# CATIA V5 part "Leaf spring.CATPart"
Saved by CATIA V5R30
Part number: Part1
Material "Steel": density 7860 kg/m3, Young's modulus 2e+11 Pa, Poisson ratio 0.266, thermal expansion 1.17e-05 1/K
Bounding box of the stored display mesh (mm): x 0 to 6, y -52.464 to 52.464, z -1 to 10.425
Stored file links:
  D:\PROJECTS\CATIA V56R 2020\Resources\Parts File\c19_catia_v5_6r2020_inp\c19_catia_v5_6r2020_inp\c19_catia_v5_6r2020_inp\C19_tut_03.CATPart\Leaf spring.CATPart
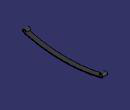
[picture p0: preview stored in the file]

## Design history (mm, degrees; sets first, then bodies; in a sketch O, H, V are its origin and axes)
Body1 (main body), material "Steel"
  Sketch1 on yz-plane, origin (0, 0, 0), H (0, 1, 0), V (0, 0, 1)
    arc A1 centre (0, 199) radius 199 from (-50.3797, 6.4828) to (50.3797, 6.4828) ccw
    point P1 (0, 199)
    arc A2 centre (0, 199) radius 200 from (-50.6329, 5.5154) to (50.6329, 5.5154) ccw
    arc A3 centre (-50, 7.9339) radius 2.5 from (-47.5, 7.9339) to (-50.6329, 5.5154) ccw
    point P2 (-50, 7.9339)
    arc A4 centre (50, 7.9339) radius 2.5 from (47.5, 7.9339) to (50.6329, 5.5154) cw
    arc A5 centre (-50, 7.9339) radius 1.5 from (-48.5, 7.9339) to (-50.3797, 6.4828) ccw
    point P4 (50, 7.9339)
    arc A6 centre (50, 7.9339) radius 1.5 from (48.5, 7.9339) to (50.3797, 6.4828) cw
    point P8 (50.3797, 6.4828)
    line L1 (48.5, 7.9339) -> (47.5, 7.9339)
    point P10 (-47.5, 7.9339)
    point P11 (50.3797, 6.4828)
    line L2 (-47.5, 7.9339) -> (-48.5, 7.9339)
    distance A1 A2 = 1
    distance P4 P2 = 100
    radius A3 = 2.5
    radius A2 = 200
    coincidence: A1 O, P1 V, A6 P8, L1 P10, A1 P11, L1 L2, L2 P2
    concentricity: A1 A2
    tangency: A3 A2, A5 A1
    symmetry: A3 A4 V, A5 A6 V
    horizontal: L1 H, L2 H
  Pad1: profile Sketch1, direction (1, 0, 0), length 6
